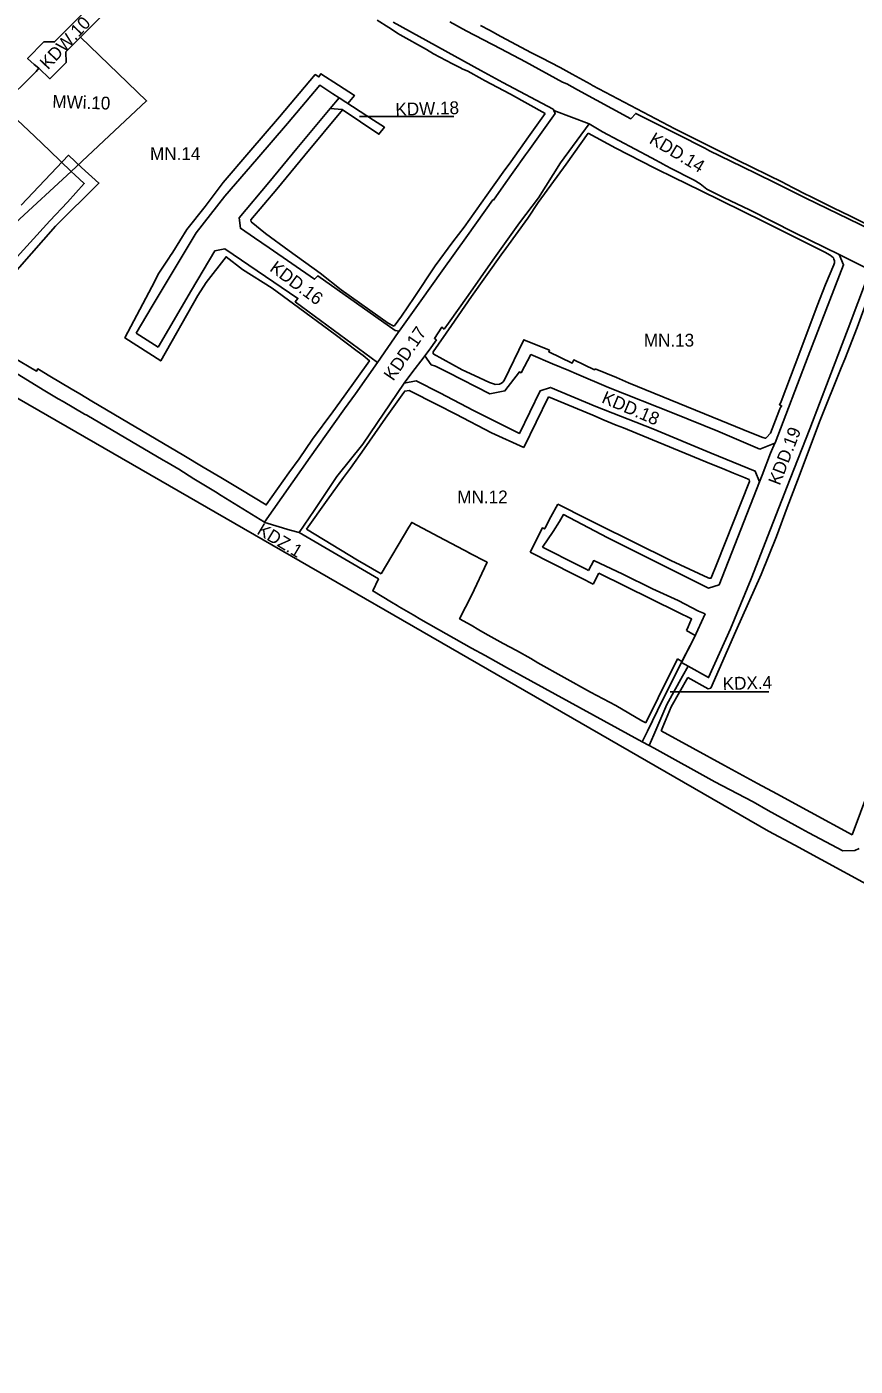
# Model space of a CAD drawing. Extents: x 7418991 to 7423142, y 5547704 to 5549547.
# Drawn here: x 7420035 to 7420359, y 5547758 to 5548281 of the extents above; entities that cross this region are included whole.
import ezdxf

# ---------------------------------------------------------------- set-up
doc = ezdxf.new("R2010")
doc.units = 0
for name, color, linetype in [('LIN_Linia Zabudowy Nieprzekraczalna', 7, 'Continuous'), ('LIN_linie_rozgraniczajace', 7, 'Continuous'), ('TXT_Oznaczenia_przeznaczen', 7, 'Continuous')]:
    doc.layers.add(name, color=color, linetype=linetype)

msp = doc.modelspace()

# ---------------------------------------------------------------- linework, layer by layer
at = {"layer": 'LIN_Linia Zabudowy Nieprzekraczalna'}
for p, q in [((7420323.11, 5548205.36), (7420298.54, 5548217.45)), ((7420257.27, 5548147.8), (7420265.63, 5548144.41)), ((7420265.63, 5548144.41), (7420270.31, 5548142.27)), ((7420195.67, 5548133.67), (7420184.55, 5548139.31)), ((7420239, 5548136.74), (7420229.39, 5548116.94)), ((7420357.76, 5547965.61), (7420407.03, 5548097.79)), ((7420258.67, 5548067.83), (7420256.48, 5548063.55)), ((7420234.84, 5548032.85), (7420255.51, 5548021.34)), ((7420301.45, 5548022.6), (7420293.47, 5548027.07)), ((7420255.51, 5548021.34), (7420265.39, 5548016.08)), ((7420265.39, 5548016.08), (7420275.53, 5548010.18)), ((7420275.53, 5548010.18), (7420277.13, 5548009.38)), ((7420283.05, 5548006.25), (7420307.83, 5547992.65))]:
    msp.add_line(p, q, dxfattribs=at)
for points in [[(7420237.78, 5548247.63), (7420224.14, 5548255.15), (7420214.05, 5548260.52), (7420213.07, 5548261.03), (7420207.42, 5548264.13), (7420205.33, 5548265.07), (7420204.63, 5548265.38), (7420201.48, 5548267.03), (7420194.08, 5548270.96), (7420191.28, 5548272.61), (7420181.08, 5548278.29), (7420180.07, 5548278.89), (7420179.13, 5548279.52), (7420176.65, 5548281.16), (7420171.96, 5548284.09)], [(7420212.5, 5548282.01), (7420215.9, 5548280.19), (7420220.39, 5548277.7), (7420232.4, 5548271.36), (7420236.25, 5548269.36), (7420243.64, 5548265.5), (7420248.34, 5548262.97), (7420255.48, 5548258.99), (7420256.2, 5548258.54), (7420288.42, 5548241.57), (7420312.72, 5548229.46), (7420330.8, 5548220.58), (7420331.71, 5548220.1), (7420335.28, 5548218.27), (7420339.59, 5548216.1), (7420341.3, 5548215.25), (7420350.43, 5548210.76), (7420357.19, 5548207.4), (7420365.46, 5548203.28)], [(7420029.5, 5548152.36), (7420038.8, 5548146.89), (7420039.29, 5548147.72), (7420039.99, 5548147.31), (7420043.93, 5548144.91), (7420052.28, 5548139.95), (7420055.78, 5548137.92), (7420060.41, 5548135.17), (7420071.85, 5548128.3), (7420096.34, 5548113.83), (7420104.02, 5548109.24), (7420110.84, 5548105.3), (7420114.81, 5548102.86), (7420118.64, 5548100.58), (7420128.64, 5548094.56), (7420137.49, 5548107.1), (7420141.53, 5548112.59), (7420146.74, 5548120.25), (7420154.71, 5548130.91), (7420159.15, 5548137.12), (7420168.97, 5548150.88), (7420166.61, 5548153.02), (7420164.24, 5548154.68), (7420155.61, 5548161.22), (7420139.36, 5548173.11), (7420130.97, 5548179.28), (7420119.39, 5548186.53), (7420112.92, 5548191.56), (7420105.12, 5548181.45), (7420101.86, 5548176.45), (7420087.36, 5548150.84), (7420073.34, 5548159.81), (7420083.87, 5548179.77), (7420086.63, 5548185.13), (7420090.82, 5548191.43), (7420090.98, 5548191.7), (7420092.08, 5548193.36), (7420097.63, 5548202.27), (7420104.74, 5548211.23), (7420111.74, 5548220.57), (7420121.88, 5548232.29), (7420133.85, 5548246.31), (7420147.83, 5548262.77), (7420149.24, 5548261.87), (7420150.01, 5548263.11), (7420156.84, 5548258.62), (7420163.12, 5548254.67), (7420160.5, 5548251.52)], [(7420158.41, 5548249), (7420143.7, 5548231.29), (7420132.73, 5548218.02), (7420122.66, 5548206.01)], [(7420178.65, 5548164.42), (7420181.48, 5548168.29), (7420186.55, 5548175.67), (7420194.77, 5548188.04), (7420201.64, 5548197.36), (7420206.05, 5548203.13), (7420214.91, 5548215.6), (7420221.36, 5548224.67), (7420224.27, 5548228.7), (7420231.24, 5548238.47), (7420237.78, 5548247.63)], [(7420254.55, 5548239.85), (7420245.93, 5548227.76), (7420234.98, 5548212.78), (7420230.93, 5548206.67), (7420222.36, 5548194.86), (7420220.48, 5548192.29), (7420208.87, 5548176.06), (7420201.08, 5548164.72), (7420193.88, 5548154.35), (7420193.96, 5548153.67)], [(7420298.54, 5548217.45), (7420288.07, 5548222.59), (7420281.12, 5548225.92), (7420280.36, 5548226.39), (7420265.4, 5548233.98), (7420254.55, 5548239.85)], [(7420032.76, 5548211.73), (7420051.25, 5548231.24), (7420056.43, 5548226.53), (7420063.21, 5548220.4), (7420046.24, 5548203.58), (7420027.46, 5548182.2)], [(7420122.66, 5548206.01), (7420122.73, 5548205.23), (7420128.39, 5548200.67), (7420137.54, 5548193.85), (7420149.73, 5548185.18), (7420158, 5548178.69), (7420176.36, 5548165.65), (7420178.27, 5548164.59), (7420178.65, 5548164.42)], [(7420350.52, 5548191.09), (7420349.26, 5548192.19), (7420347.17, 5548193.38), (7420340.9, 5548196.49), (7420333.88, 5548200.03), (7420323.11, 5548205.36)], [(7420329.43, 5548133.61), (7420330, 5548135.02), (7420337.39, 5548154.29), (7420344.09, 5548172.35), (7420347.42, 5548180.76), (7420350.69, 5548188.47), (7420350.89, 5548189.15), (7420350.9, 5548189.91), (7420350.69, 5548190.68), (7420350.52, 5548191.09)], [(7420368.86, 5548182.46), (7420368.52, 5548182.5), (7420367.76, 5548182.46), (7420367.22, 5548182.33), (7420366.84, 5548182.12), (7420366.82, 5548182.1), (7420366.62, 5548181.75), (7420362.34, 5548171.05), (7420359.73, 5548163.94), (7420354.9, 5548151.56)], [(7420210.09, 5548145.1), (7420215.91, 5548142.36), (7420217.89, 5548141.72), (7420218.23, 5548141.67), (7420219.83, 5548141.8), (7420220.1, 5548141.85), (7420220.45, 5548141.99), (7420221.05, 5548142.41), (7420221.2, 5548142.56), (7420221.66, 5548143.21), (7420229.44, 5548159.09), (7420239.49, 5548155.01)], [(7420239.49, 5548155.01), (7420239.18, 5548154.34), (7420248.32, 5548149.98), (7420248.91, 5548151.21), (7420257.07, 5548147.39), (7420257.27, 5548147.8)], [(7420193.96, 5548153.67), (7420205.31, 5548147.33), (7420210.09, 5548145.1)], [(7420354.9, 5548151.56), (7420353.48, 5548148.13), (7420345.35, 5548127.64), (7420336.48, 5548104.03), (7420332.38, 5548093.55), (7420328.16, 5548082.23), (7420322.23, 5548067.28), (7420312.29, 5548045.18)], [(7420184.55, 5548139.31), (7420182.81, 5548139.02), (7420182.42, 5548138.52), (7420175.32, 5548128.43), (7420166.98, 5548116.45), (7420161.53, 5548108.9), (7420158.91, 5548105.2), (7420152.49, 5548096.34), (7420144.33, 5548085.02)], [(7420270.31, 5548142.27), (7420306.47, 5548127.6), (7420317.89, 5548122.88), (7420322.84, 5548120.96), (7420323.8, 5548120.6), (7420323.98, 5548120.61), (7420324.31, 5548120.88), (7420325.83, 5548122.57)], [(7420229.39, 5548116.94), (7420216.71, 5548122.76), (7420202.73, 5548129.97), (7420195.67, 5548133.67)], [(7420317.6, 5548103.64), (7420317.46, 5548104.47), (7420317.12, 5548104.67), (7420315.99, 5548105.11), (7420311.43, 5548106.97), (7420307.08, 5548108.78), (7420306.1, 5548109.15), (7420300.63, 5548111.33), (7420273.74, 5548122.41), (7420268.36, 5548124.65), (7420265.5, 5548125.78), (7420260.87, 5548127.72), (7420256.32, 5548129.65), (7420239, 5548136.74)], [(7420325.83, 5548122.57), (7420329.15, 5548131.09), (7420329.54, 5548132.07), (7420329.88, 5548132.95), (7420330.01, 5548132.92), (7420330.17, 5548133.32), (7420330.04, 5548133.38), (7420329.43, 5548133.61)], [(7420242.69, 5548094.87), (7420254.34, 5548088.99), (7420258.25, 5548087.08), (7420286.87, 5548072.87), (7420301.51, 5548066.04), (7420301.92, 5548065.95), (7420302.21, 5548065.91), (7420302.38, 5548065.92), (7420302.6, 5548065.96), (7420302.68, 5548065.99), (7420304.82, 5548071.48), (7420317.6, 5548103.64)], [(7420231.91, 5548076.02), (7420236.65, 5548085.53), (7420237.51, 5548085.14), (7420237.72, 5548085.56), (7420239.89, 5548089.92), (7420242.69, 5548094.87)], [(7420173.63, 5548067.54), (7420184.47, 5548085.81), (7420185.53, 5548087.73), (7420196.2, 5548082.1), (7420208.29, 5548075.66)], [(7420144.33, 5548085.02), (7420164.35, 5548072.92), (7420173.63, 5548067.54)], [(7420256.48, 5548063.55), (7420251.91, 5548065.88), (7420248.84, 5548067.43), (7420231.91, 5548076.02)], [(7420207.87, 5548075.83), (7420214.99, 5548072.11), (7420208.97, 5548059.12), (7420204.26, 5548050.02), (7420208.79, 5548047.47), (7420211.81, 5548045.65)], [(7420293.04, 5548045.5), (7420293.72, 5548046.84), (7420294.99, 5548049.96), (7420289.65, 5548052.61), (7420258.67, 5548067.83)], [(7420211.81, 5548045.65), (7420214.3, 5548044.28), (7420221.24, 5548040.42), (7420226.52, 5548037.69), (7420232.17, 5548034.49), (7420234.84, 5548032.85)], [(7420289.51, 5548034.35), (7420291.25, 5548033.35), (7420296.01, 5548042.62), (7420296.4, 5548043.55), (7420293.04, 5548045.5)], [(7420312.31, 5548045.23), (7420302.52, 5548022.89), (7420301.45, 5548022.6)], [(7420277.13, 5548009.38), (7420281.88, 5548019.1), (7420289.51, 5548034.35)], [(7420293.47, 5548027.07), (7420287.06, 5548015.58), (7420283.05, 5548006.25)], [(7420307.83, 5547992.65), (7420320.72, 5547985.62), (7420328.32, 5547981.6)], [(7420328.32, 5547981.6), (7420341.55, 5547974.39), (7420357.76, 5547965.61)]]:
    msp.add_lwpolyline(points, dxfattribs=at)
at = {"layer": 'LIN_linie_rozgraniczajace'}
for p, q in [((7420153.66, 5548249.54), (7420157.13, 5548253.71)), ((7420254.96, 5548243.48), (7420241.1, 5548248.81)), ((7420086.37, 5548156.22), (7420077.78, 5548161.72)), ((7420321.75, 5548116.33), (7420327.61, 5548118.65))]:
    msp.add_line(p, q, dxfattribs=at)
for points in [[(7420111.92, 5548329.58), (7420111.91, 5548329.57), (7420103.38, 5548321.17), (7420095.97, 5548313.59), (7420086.63, 5548308.14), (7420082.78, 5548304.28), (7420069.37, 5548290.83), (7420055.95, 5548277.38), (7420050.3, 5548271.71), (7420050.35, 5548267.51), (7420043.99, 5548261.14), (7420039.67, 5548265.29), (7420037.82, 5548266.71), (7420035.28, 5548269.12), (7420041.67, 5548275.57), (7420045.88, 5548275.57), (7420052.97, 5548282.76), (7420067.6, 5548297.55), (7420082.18, 5548312.32)], [(7420212.54, 5548264.35), (7420178.28, 5548283.31)], [(7420426.22, 5548171.99), (7420415.22, 5548177.66), (7420402.67, 5548183.82), (7420390.43, 5548189.74), (7420377.56, 5548196.15), (7420364.97, 5548202.2), (7420352.34, 5548208.3), (7420339.71, 5548214.44), (7420327.19, 5548220.68), (7420314.67, 5548226.85), (7420302.07, 5548233.01), (7420300.21, 5548233.96), (7420289.57, 5548239.37), (7420273.14, 5548247.62), (7420271.3, 5548245.54), (7420250.38, 5548256.86), (7420246.18, 5548259.13), (7420244.57, 5548259.84), (7420230.05, 5548267.75), (7420220.41, 5548272.9), (7420206.86, 5548279.87), (7420200.41, 5548283.37)], [(7420055.95, 5548277.38), (7420081.86, 5548252.52), (7420067.24, 5548238.84), (7420052.3, 5548224.88), (7420044.01, 5548232.93), (7420038.12, 5548238.54), (7420033.38, 5548243.06), (7420025.21, 5548250.74), (7420038.69, 5548264.06), (7420039.67, 5548265.29)], [(7420241.1, 5548248.81), (7420241.06, 5548248.83), (7420240.87, 5548249.22), (7420221.12, 5548259.76), (7420212.54, 5548264.35)], [(7420157.13, 5548253.71), (7420154.67, 5548255.26), (7420149.56, 5548258.62), (7420136.9, 5548243.72), (7420124.91, 5548229.68), (7420112.46, 5548215.28), (7420101.19, 5548200.92), (7420084.06, 5548172.21), (7420077.78, 5548161.72)], [(7420013.74, 5548172.54), (7420028.67, 5548188.72), (7420044.03, 5548205.64), (7420050.93, 5548212.94), (7420057.48, 5548220.19), (7420053.74, 5548223.57), (7420052.3, 5548224.88), (7420030.5, 5548204.84), (7420023.66, 5548211.31), (7420017.89, 5548216.78), (7420012.97, 5548221.44), (7420004.18, 5548229.76), (7420003, 5548230.83), (7419992.53, 5548240.75), (7419982.47, 5548250.14)], [(7420180.69, 5548162.53), (7420179.11, 5548162.75), (7420148.83, 5548184.15), (7420147.49, 5548182.77), (7420129.75, 5548195.08), (7420124.02, 5548198.93), (7420118.56, 5548202.7), (7420118.05, 5548206.73), (7420129.66, 5548220.58), (7420140.62, 5548233.84), (7420153.66, 5548249.54)], [(7420127.99, 5548087.77), (7420145.87, 5548113.18), (7420155.05, 5548126.23), (7420159.26, 5548132.16), (7420163.5, 5548137.98), (7420172.21, 5548150.19), (7420180.27, 5548161.93), (7420180.69, 5548162.53), (7420189.06, 5548174.3), (7420197.49, 5548186.1), (7420207.31, 5548199.85), (7420217.3, 5548213.85), (7420217.47, 5548213.73), (7420222.31, 5548220.62), (7420225.26, 5548224.66), (7420230.09, 5548231.43), (7420231.21, 5548232.99), (7420241.62, 5548247.56), (7420241.1, 5548248.81)], [(7420157.13, 5548253.71), (7420170.62, 5548244.94), (7420174.87, 5548242.2), (7420172.71, 5548239.44), (7420158.29, 5548249.08), (7420153.66, 5548249.54)], [(7420198.27, 5548163.29), (7420199.95, 5548165.62), (7420207.6, 5548176.4), (7420217.29, 5548190.25), (7420227.67, 5548204.85), (7420235.09, 5548214.61), (7420243.79, 5548228.24), (7420254.96, 5548243.48)], [(7420260.15, 5548240.44), (7420254.96, 5548243.48)], [(7420300.94, 5548217.98), (7420298.34, 5548220.05), (7420295.96, 5548221.52), (7420295.02, 5548222.05), (7420287.57, 5548225.84), (7420284.57, 5548227.41), (7420284.18, 5548227.62), (7420279.33, 5548230.27), (7420260.15, 5548240.44)], [(7420423.83, 5548152.38), (7420420.69, 5548157.85), (7420413.79, 5548161.36), (7420413.95, 5548161.81), (7420410.47, 5548163.15), (7420410.44, 5548163.06), (7420394.61, 5548171.11), (7420367.61, 5548184.98), (7420352.75, 5548192.43), (7420335.33, 5548200.95), (7420317.69, 5548209.94), (7420307.76, 5548214.65), (7420300.94, 5548217.98)], [(7420172.21, 5548150.19), (7420139.97, 5548173.98), (7420141.01, 5548175.3), (7420112.49, 5548194.71), (7420108.55, 5548193.92), (7420099.37, 5548178.46), (7420086.37, 5548156.22)], [(7420305.79, 5548063.34), (7420321.54, 5548103.53), (7420322.57, 5548106.14), (7420325.87, 5548114.83), (7420327.61, 5548118.65), (7420327.71, 5548118.88), (7420340.55, 5548152.66), (7420354.43, 5548188.37), (7420352.75, 5548192.43)], [(7420367.61, 5548184.98), (7420363.85, 5548183.55), (7420356.29, 5548163.48), (7420348.77, 5548144.11), (7420341.23, 5548124.28), (7420333.55, 5548104.71), (7420325.82, 5548085.01), (7420318.33, 5548065.62), (7420310.19, 5548046.16), (7420301.68, 5548027.06), (7420293.66, 5548031.55), (7420291.07, 5548033), (7420296.01, 5548042.62), (7420300.29, 5548051.94)], [(7420195.24, 5548159.08), (7420194.39, 5548159.65), (7420197.26, 5548163.98), (7420198.27, 5548163.29)], [(7420141.46, 5548083.72), (7420147.37, 5548092.39), (7420156.31, 5548105.61), (7420166.42, 5548118.29), (7420182.61, 5548142.2), (7420186.01, 5548146.7), (7420190.02, 5548151.96), (7420190.69, 5548152.84), (7420192.34, 5548155.01), (7420195.24, 5548159.08)], [(7420100.28, 5548104.74), (7420094.4, 5548108.51), (7420089.7, 5548111.23), (7420088.3, 5548112.05), (7420058.44, 5548129.6), (7420057.5, 5548130.02), (7420049.19, 5548135.03), (7420047.23, 5548136.04), (7420041.36, 5548139.54), (7420021.57, 5548151.65), (7420020.65, 5548152.15)], [(7420321.75, 5548116.33), (7420305.23, 5548123.39), (7420288.21, 5548130.31), (7420262.53, 5548140.51), (7420249.93, 5548145.75), (7420246.94, 5548147.09), (7420240.61, 5548149.71), (7420232.15, 5548153.33), (7420228.28, 5548146.23), (7420227.74, 5548146.6), (7420221.96, 5548139.14), (7420216.04, 5548137.93), (7420199.8, 5548146.3), (7420194.9, 5548148.73), (7420193.2, 5548149.36), (7420190.69, 5548152.84)], [(7420691.26, 5547757.8), (7420643.94, 5547767.55), (7420631.35, 5547769.73), (7420617.94, 5547773.51), (7420614.35, 5547774.52), (7420596.92, 5547781.46), (7420594.97, 5547782.69), (7420583.1, 5547790.25), (7420570.22, 5547800.34), (7420556.17, 5547816.42), (7420528.6, 5547856.05), (7420513.96, 5547871.91), (7420496.43, 5547886.53), (7420482.51, 5547895.88), (7420465.97, 5547902.98), (7420428.16, 5547915.6), (7420393.16, 5547930.85), (7420375.21, 5547939.92), (7420335.32, 5547961.49), (7420325.12, 5547967), (7420017.42, 5548144.29)], [(7420182.61, 5548142.2), (7420187.34, 5548143.03), (7420196.49, 5548138.31), (7420209.75, 5548131.41), (7420227.65, 5548122.52), (7420235.72, 5548139.15), (7420239.81, 5548140.51), (7420257.6, 5548133.06), (7420279.79, 5548124.29), (7420302.6, 5548114.79), (7420319.91, 5548107.74), (7420321.54, 5548103.53)], [(7420141.46, 5548083.72), (7420138.03, 5548084.61), (7420128.15, 5548087.67), (7420127.99, 5548087.77), (7420111.01, 5548098.25), (7420108.77, 5548099.6), (7420100.28, 5548104.74)], [(7420305.79, 5548063.34), (7420301.59, 5548061.99), (7420283.35, 5548071.17), (7420262.03, 5548081.82), (7420244.84, 5548090.74), (7420243.32, 5548088.1), (7420240.8, 5548084.18), (7420236.75, 5548078.05)], [(7420340.9, 5547966.34), (7420337.99, 5547967.89), (7420324.96, 5547975.08), (7420319.05, 5547978.46), (7420315.85, 5547980.2), (7420304.1, 5547986.32), (7420280.3, 5547999.41), (7420278.39, 5548000.46), (7420275.72, 5548001.92), (7420222.63, 5548030.97), (7420214.2, 5548035.69), (7420208.94, 5548038.58), (7420189.08, 5548049.81), (7420186.07, 5548051.59), (7420180.65, 5548054.7), (7420179.78, 5548055.23), (7420177.65, 5548056.53), (7420170.27, 5548060.95), (7420172.49, 5548065.6), (7420141.46, 5548083.72)], [(7420236.75, 5548078.05), (7420250.64, 5548071), (7420253.72, 5548069.45), (7420254.74, 5548068.93)], [(7420300.29, 5548051.94), (7420297.7, 5548053.04), (7420289.71, 5548057.13), (7420279.71, 5548061.74), (7420268.07, 5548067.48), (7420256.71, 5548072.78), (7420254.74, 5548068.93)], [(7420291.07, 5548033), (7420283.67, 5548018.21), (7420277.74, 5548006.06), (7420275.72, 5548001.92)], [(7420293.66, 5548031.55), (7420291.5, 5548027.65), (7420285.26, 5548016.46), (7420280.18, 5548004.63), (7420278.39, 5548000.46)], [(7420360.58, 5547960.26), (7420358.8, 5547959.42), (7420354.1, 5547959.29), (7420340.9, 5547966.34)]]:
    msp.add_lwpolyline(points, dxfattribs=at)
at = {"layer": 'TXT_Oznaczenia_przeznaczen'}
for p, q in [((7420165.07, 5548246.41), (7420201.98, 5548246.41)), ((7420286.62, 5548021.46), (7420325.2, 5548021.46))]:
    msp.add_line(p, q, dxfattribs=at)

# ---------------------------------------------------------------- texts
for s, rotation, p in [('KDW.10', 46.655, (7420043.21, 5548264.47)), ('MWi.10', 357.9964, (7420044.92, 5548249.88)), ('KDW.18', 1.6002, (7420179.22, 5548246.69)), ('KDD.14', 329.1162, (7420278.06, 5548236.23)), ('KDD.16', 323.4432, (7420129.63, 5548186.33)), ('KDD.17', 55.5706, (7420178.31, 5548142.71)), ('KDD.18', 336.9342, (7420259.47, 5548134.68)), ('KDD.19', 68.8884, (7420329.49, 5548101.89)), ('KDZ.1', 329.093, (7420124.62, 5548083.42)), ('KDX.4', 1.6195, (7420307.23, 5548022.16))]:
    msp.add_text(s, height=5, rotation=rotation, dxfattribs=at).set_placement(p)
for s, p in [('MN.14', (7420083.18, 5548229.39)), ('MN.13', (7420276.3, 5548156.46)), ('MN.12', (7420203.37, 5548095.17))]:
    msp.add_text(s, height=5, dxfattribs=at).set_placement(p)

doc.saveas('drawing.dxf')
